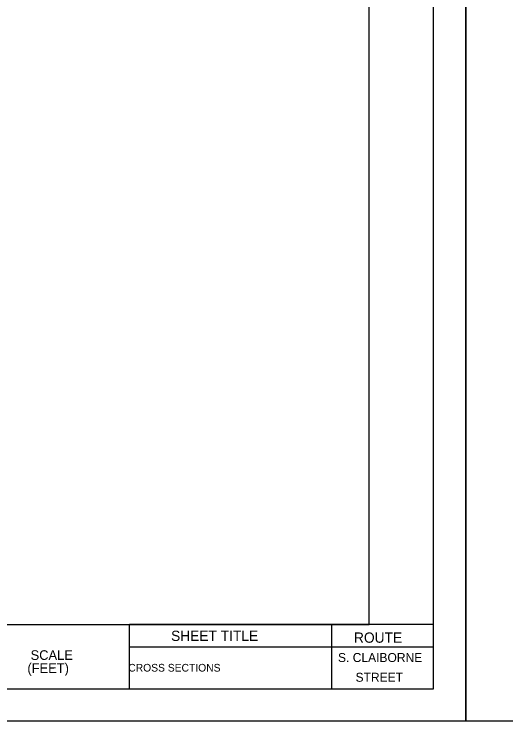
# Model space of a CAD drawing. Extents: x 1797478 to 1803816, y 246529 to 250952.
# Drawn here: x 1802385.7 to 1802462.3, y 250064.4 to 250174.4 of the extents above; entities that cross this region are included whole.
import ezdxf

# ---------------------------------------------------------------- set-up
doc = ezdxf.new("R2010")
doc.units = 0
for name, color, linetype in [('ANNO-SHT', 7, 'Continuous'), ('ANNO-SYMB', 7, 'Continuous'), ('ANNO-TXT', 7, 'Continuous'), ('Level 6', 7, 'Continuous'), ('Level 62', 7, 'Continuous'), ('SHT-BDR', 7, 'Continuous'), ('SHT-BNDRY', 7, 'Continuous')]:
    doc.layers.add(name, color=color, linetype=linetype)

msp = doc.modelspace()

# ---------------------------------------------------------------- linework, layer by layer
at = {"layer": 'ANNO-TXT'}
for p, q in [((1802403.66, 250075.96), (1802435.19, 250075.96)), ((1802435.19, 250075.96), (1802451, 250075.96))]:
    msp.add_line(p, q, dxfattribs=at)
at = {"layer": 'Level 6'}
msp.add_line((1802451, 250079.43), (1802403.66, 250079.43), dxfattribs=at)
at = {"layer": 'Level 62'}
for points in [[(1802116, 250064.42), (1802456, 250064.42), (1802456, 250284.42), (1802116, 250284.42)], [(1802456, 250064.42), (1802796, 250064.42), (1802796, 250284.42), (1802456, 250284.42)]]:
    msp.add_lwpolyline(points, close=True, dxfattribs=at)
at = {"layer": 'SHT-BDR'}
msp.add_lwpolyline([(1802141, 250079.43), (1802441, 250079.43), (1802441, 250269.43), (1802141, 250269.43)], close=True, dxfattribs=at)
at = {"layer": 'SHT-BNDRY'}
for p, q in [((1802403.66, 250069.42), (1802403.66, 250079.43)), ((1802435.19, 250069.42), (1802435.19, 250079.43))]:
    msp.add_line(p, q, dxfattribs=at)
msp.add_lwpolyline([(1802128.5, 250069.42), (1802451, 250069.42), (1802451, 250279.42), (1802128.5, 250279.42)], close=True, dxfattribs=at)

# ---------------------------------------------------------------- texts
at = {"layer": 'ANNO-SHT'}
for s, height, p in [('S. CLAIBORNE', 1.4, (1802436.13, 250073.58)), ('          CROSS SECTIONS          ', 1.2, (1802399.03, 250072.09)), (' STREET', 1.4, (1802438.34, 250070.51))]:
    msp.add_text(s, height=height, rotation=360, dxfattribs=at).set_placement(p)
at = {"layer": 'ANNO-SYMB'}
for s, p in [('SCALE', (1802388.29, 250073.91)), ('(FEET)', (1802387.79, 250071.88))]:
    msp.add_text(s, height=1.499, rotation=0.0572, dxfattribs=at).set_placement(p)
at = {"layer": 'ANNO-TXT'}
for s, p in [('SHEET TITLE', (1802410.15, 250076.86)), ('ROUTE', (1802438.62, 250076.58))]:
    msp.add_text(s, height=1.6, dxfattribs=at).set_placement(p)

doc.saveas('drawing.dxf')
